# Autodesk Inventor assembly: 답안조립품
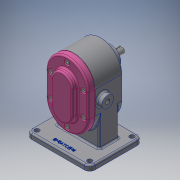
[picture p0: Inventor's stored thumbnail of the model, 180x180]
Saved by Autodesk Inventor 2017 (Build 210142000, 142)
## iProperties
Part Number: 답안조립품
Material: 일반
Document SubType Name: Assembly
Designer: 00-00
Author: 00-00
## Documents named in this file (11)
- C:\Users\00-00\Desktop\700906V1046\답안조립품.iam
- C:\Users\00-00\Desktop\700906V1046\본체.ipt
- C:\Users\00-00\Desktop\700906V1046\메인축.ipt
- C:\Users\00-00\Desktop\700906V1046\키 6 x 6 x 18.ipt
- C:\Users\00-00\Desktop\700906V1046\스퍼기어.ipt
- C:\Users\00-00\Desktop\700906V1046\베어링부시.ipt
- C:\Users\00-00\Desktop\700906V1046\서브축.ipt
- C:\Users\00-00\Desktop\700906V1046\개스킷.ipt
- C:\Users\00-00\Desktop\700906V1046\커버.ipt
- C:\Users\00-00\Desktop\700906V1046\오일 실 16 28 7.ipt
- C:\Users\00-00\Desktop\700906V1046\볼트 M5.ipt
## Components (1 placed, 1 different names)
1. 개스킷:1
